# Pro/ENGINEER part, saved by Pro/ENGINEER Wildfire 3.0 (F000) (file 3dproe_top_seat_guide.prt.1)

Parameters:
  DESCRIPTION = "COMPRESSION NUT - 6"
  MODELED_BY = "L. CONARD"
  PTC_COMMON_NAME = "COMPRESSION NUT - 6"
